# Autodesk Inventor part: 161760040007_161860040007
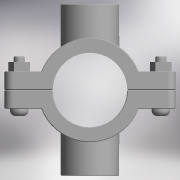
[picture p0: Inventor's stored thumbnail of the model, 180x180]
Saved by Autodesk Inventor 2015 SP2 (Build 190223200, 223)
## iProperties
Created: 2017-05
Part Number: 161760040007_161860040007
Material: Generic
Description: PLASSON DOUBLE SADDLE 40-3/4"
Document SubType Name: Modeling
Designer: KIM
Density: 1 g/cm^3
Appearance: Default
Author: KIM
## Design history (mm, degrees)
derived "16176.ipt"
feature "Solid1::16176.ipt"
feature "Solid2::16176.ipt"
tag "TaggingFeature1"
body "Solid1"
body "Solid2"
other parameters: "d0" = 56, "d1" = 92, "d5" = 0, "d6" = 4.6, "d7" = 92, "d8" = 0.1, "d10" = 0, "d11" = 0.4, "d20" = 0.4, "d23" = 0.4, "d37" = 8, "d38" = 28, "d39" = 0, "d40" = 3, "d41" = 5, "d42" = 0, "d43" = 6, "d44" = 3, "d45" = 0, "d46" = 0.4, "d52" = 24.117, "d53" = 19, "d54" = 0, "d55" = 19, "d57" = 0, "d58" = 43.2, "d60" = 0, "d66" = 0, "d67" = 92, "d68" = 31.3521, "d69" = 24.117, "d70" = 19, "d71" = 0, "d72" = 19, "d74" = 0, "d75" = 0.4, "B_" = 19, "G_" = 24.117, "A_" = 46, "L_" = 92, "l_2" = 19
